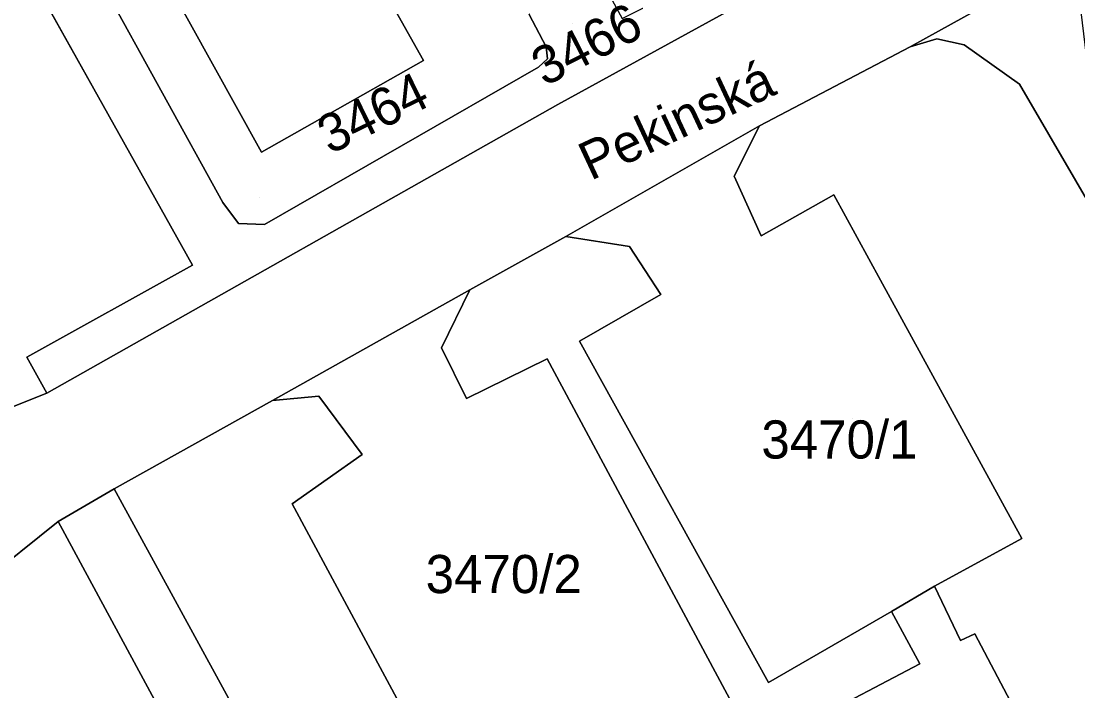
# Model space of a CAD drawing. Extents: x -262715 to -259381, y -1237238 to -1231182.
# Drawn here: x -261471.4 to -261416.1, y -1235520.8 to -1235485.7 of the extents above; entities that cross this region are included whole.
import ezdxf

# ---------------------------------------------------------------- set-up
doc = ezdxf.new("R2010")
doc.units = 0
for name, color, linetype in [('body_kn', 7, 'Continuous'), ('kladpar_druhypozemkov', 7, 'Continuous'), ('kladpar_hranice', 7, 'Continuous'), ('kladpar_parcelnecisla', 7, 'Continuous'), ('kladpar_plochy', 7, 'Continuous'), ('popisy', 7, 'Continuous')]:
    doc.layers.add(name, color=color, linetype=linetype)

msp = doc.modelspace()

# ---------------------------------------------------------------- linework, layer by layer
at = {"layer": 'body_kn'}
for p, q in [((-261423.49, -1235486.65), (-261423.49, -1235486.65)), ((-261443.95, -1235487.06), (-261443.95, -1235487.06)), ((-261424.88, -1235487.06), (-261424.88, -1235487.06)), ((-261422.06, -1235486.95), (-261422.06, -1235486.95)), ((-261450.37, -1235487.77), (-261450.37, -1235487.77)), ((-261443.88, -1235487.69), (-261443.88, -1235487.69)), ((-261444.35, -1235488.12), (-261444.35, -1235488.12)), ((-261419.15, -1235489.02), (-261419.15, -1235489.02)), ((-261419.15, -1235489.02), (-261419.15, -1235489.02)), ((-261443.34, -1235490.09), (-261443.34, -1235490.09)), ((-261432.77, -1235491.2), (-261432.77, -1235491.2)), ((-261458.86, -1235492.58), (-261458.86, -1235492.58)), ((-261434.11, -1235493.83), (-261434.11, -1235493.83)), ((-261428.88, -1235494.81), (-261428.88, -1235494.81)), ((-261428.88, -1235494.81), (-261428.88, -1235494.81)), ((-261460.89, -1235495.22), (-261460.89, -1235495.22)), ((-261460.06, -1235496.32), (-261460.06, -1235496.32)), ((-261458.71, -1235496.37), (-261458.71, -1235496.37)), ((-261442.92, -1235497), (-261442.92, -1235497)), ((-261432.68, -1235496.96), (-261432.68, -1235496.96)), ((-261439.58, -1235497.52), (-261439.58, -1235497.52)), ((-261462.48, -1235498.5), (-261462.48, -1235498.5)), ((-261426.44, -1235499.28), (-261426.44, -1235499.28)), ((-261447.95, -1235499.79), (-261447.95, -1235499.79)), ((-261437.95, -1235500.04), (-261437.95, -1235500.04)), ((-261437.95, -1235500.04), (-261437.95, -1235500.04)), ((-261442.21, -1235502.48), (-261442.21, -1235502.48)), ((-261471.16, -1235503.32), (-261471.16, -1235503.32)), ((-261449.43, -1235502.83), (-261449.43, -1235502.83)), ((-261443.89, -1235503.41), (-261443.89, -1235503.41)), ((-261443.89, -1235503.41), (-261443.89, -1235503.41)), ((-261470.11, -1235505.2), (-261470.11, -1235505.2)), ((-261455.85, -1235505.36), (-261455.85, -1235505.36)), ((-261448.12, -1235505.48), (-261448.12, -1235505.48)), ((-261458.29, -1235505.58), (-261458.29, -1235505.58)), ((-261453.58, -1235508.42), (-261453.58, -1235508.42)), ((-261466.57, -1235510.22), (-261466.57, -1235510.22)), ((-261466.57, -1235510.22), (-261466.57, -1235510.22)), ((-261457.25, -1235511), (-261457.25, -1235511)), ((-261469.51, -1235511.93), (-261469.51, -1235511.93)), ((-261469.51, -1235511.93), (-261469.51, -1235511.93)), ((-261419.04, -1235512.81), (-261419.04, -1235512.81)), ((-261423.61, -1235515.31), (-261423.61, -1235515.31)), ((-261425.86, -1235516.64), (-261425.86, -1235516.64)), ((-261422.25, -1235518.17), (-261422.25, -1235518.17)), ((-261421.49, -1235517.81), (-261421.49, -1235517.81)), ((-261424.38, -1235519.39), (-261424.38, -1235519.39)), ((-261432.31, -1235520.36), (-261432.31, -1235520.36))]:
    msp.add_line(p, q, dxfattribs=at)
at = {"layer": 'kladpar_druhypozemkov'}
for p, q in [((-261442.58, -1235485.86), (-261442.58, -1235485.86)), ((-261458.99, -1235494.98), (-261458.99, -1235494.98)), ((-261427.93, -1235506.53), (-261427.93, -1235506.53)), ((-261444.85, -1235513.54), (-261444.85, -1235513.54))]:
    msp.add_line(p, q, dxfattribs=at)
at = {"layer": 'kladpar_hranice'}
for points in [[(-261500.9, -1235423.36), (-261498.98, -1235427.43), (-261501.9, -1235429.04), (-261472.92, -1235479.85), (-261462.48, -1235498.5), (-261471.16, -1235503.32), (-261470.11, -1235505.2), (-261474.22, -1235506.84), (-261480.34, -1235505.93), (-261486.88, -1235501.6)], [(-261377.82, -1235426.4), (-261370.31, -1235440.22), (-261369.19, -1235443.16), (-261369.47, -1235446.47), (-261370.9, -1235449.61), (-261420.3, -1235477.43), (-261443.34, -1235490.09), (-261470.11, -1235505.2), (-261471.16, -1235503.32), (-261462.48, -1235498.5), (-261472.92, -1235479.85)], [(-261474.22, -1235506.84), (-261470.11, -1235505.2), (-261443.34, -1235490.09), (-261420.3, -1235477.43), (-261370.9, -1235449.61), (-261357.67, -1235441.76), (-261352.68, -1235439.16)], [(-261352.68, -1235439.16), (-261349.41, -1235444.59), (-261351.54, -1235445.98), (-261368.97, -1235455.57), (-261380.71, -1235462.13), (-261384.52, -1235464.26), (-261395.59, -1235470.52), (-261399.31, -1235472.78), (-261411.78, -1235479.68), (-261414.81, -1235481.47), (-261424.88, -1235487.06), (-261432.77, -1235491.2), (-261442.92, -1235497), (-261447.95, -1235499.79), (-261458.29, -1235505.58), (-261466.57, -1235510.22), (-261469.51, -1235511.93), (-261473.53, -1235515.14)], [(-261477.08, -1235466.16), (-261470.37, -1235478.02), (-261460.89, -1235495.22), (-261460.06, -1235496.32), (-261458.71, -1235496.37), (-261444.35, -1235488.12), (-261443.88, -1235487.69), (-261443.95, -1235487.06), (-261445.94, -1235483.26), (-261442.3, -1235481.26), (-261439.97, -1235485.57), (-261435.82, -1235483.49), (-261433.64, -1235482.27), (-261421.07, -1235475.1), (-261418.7, -1235473.78), (-261410.55, -1235469.33)], [(-261448.11, -1235471.56), (-261442.95, -1235480.09), (-261442.3, -1235481.26), (-261445.94, -1235483.26), (-261449.32, -1235485.12), (-261449.92, -1235484.05), (-261451.86, -1235485.14), (-261450.37, -1235487.77), (-261458.86, -1235492.58), (-261467.71, -1235476.61), (-261459.76, -1235472.06), (-261458.19, -1235475), (-261452.66, -1235472.13), (-261451.77, -1235473.6), (-261448.11, -1235471.56)], [(-261445.94, -1235483.26), (-261443.95, -1235487.06), (-261443.88, -1235487.69), (-261444.35, -1235488.12), (-261458.71, -1235496.37), (-261460.06, -1235496.32), (-261460.89, -1235495.22), (-261470.37, -1235478.02), (-261467.71, -1235476.61), (-261458.86, -1235492.58), (-261450.37, -1235487.77), (-261451.86, -1235485.14), (-261449.92, -1235484.05), (-261449.32, -1235485.12), (-261445.94, -1235483.26)], [(-261403.59, -1235514.32), (-261406.6, -1235515.95), (-261408.97, -1235508.66), (-261408.65, -1235507.05), (-261419.15, -1235489.02), (-261422.06, -1235486.95), (-261423.49, -1235486.65), (-261424.88, -1235487.06), (-261414.81, -1235481.47)], [(-261341.24, -1235665.13), (-261362.46, -1235627.19), (-261408.87, -1235541.7), (-261411.85, -1235536.79), (-261410.98, -1235536.3), (-261416.37, -1235525.37), (-261417.25, -1235525.86), (-261421.49, -1235517.81), (-261422.25, -1235518.17), (-261423.61, -1235515.31), (-261419.04, -1235512.81), (-261426.44, -1235499.28), (-261428.88, -1235494.81), (-261432.68, -1235496.96), (-261434.11, -1235493.83), (-261432.77, -1235491.2), (-261424.88, -1235487.06), (-261423.49, -1235486.65), (-261422.06, -1235486.95), (-261419.15, -1235489.02)], [(-261419.15, -1235489.02), (-261408.65, -1235507.05), (-261408.97, -1235508.66), (-261406.6, -1235515.95), (-261405.79, -1235517.45), (-261409.42, -1235519.43), (-261403.63, -1235530.87)], [(-261428.88, -1235494.81), (-261426.44, -1235499.28), (-261419.04, -1235512.81), (-261423.61, -1235515.31), (-261425.86, -1235516.64), (-261432.31, -1235520.36), (-261442.21, -1235502.48), (-261437.95, -1235500.04), (-261439.58, -1235497.52), (-261442.92, -1235497), (-261432.77, -1235491.2), (-261434.11, -1235493.83), (-261432.68, -1235496.96), (-261428.88, -1235494.81)], [(-261437.95, -1235500.04), (-261442.21, -1235502.48), (-261432.31, -1235520.36), (-261425.86, -1235516.64), (-261424.38, -1235519.39), (-261453.28, -1235534.58), (-261466.57, -1235510.22), (-261458.29, -1235505.58), (-261455.85, -1235505.36), (-261453.58, -1235508.42), (-261457.25, -1235511), (-261447.54, -1235529.06), (-261434.21, -1235521.46), (-261443.89, -1235503.41), (-261448.12, -1235505.48), (-261449.43, -1235502.83), (-261447.95, -1235499.79), (-261442.92, -1235497), (-261439.58, -1235497.52), (-261437.95, -1235500.04)], [(-261443.89, -1235503.41), (-261434.21, -1235521.46), (-261447.54, -1235529.06), (-261457.25, -1235511), (-261453.58, -1235508.42), (-261455.85, -1235505.36), (-261458.29, -1235505.58), (-261447.95, -1235499.79), (-261449.43, -1235502.83), (-261448.12, -1235505.48), (-261443.89, -1235503.41)], [(-261352.7, -1235701.57), (-261356.45, -1235698.78), (-261375.96, -1235663.31), (-261392.09, -1235634.4), (-261401.48, -1235640.18), (-261403.28, -1235637.04), (-261396.15, -1235632.64), (-261395.33, -1235631.71), (-261395.49, -1235630.29), (-261406.15, -1235610.79), (-261420.15, -1235585.99), (-261421.33, -1235584.92), (-261422.94, -1235585.32), (-261434.14, -1235591.59), (-261445.58, -1235571), (-261446.9, -1235569.53), (-261442.73, -1235566.89), (-261441.26, -1235564.87), (-261441.82, -1235562.85), (-261455.34, -1235538.18), (-261469.51, -1235511.93), (-261466.57, -1235510.22)], [(-261466.57, -1235510.22), (-261453.28, -1235534.58), (-261424.38, -1235519.39), (-261425.86, -1235516.64), (-261423.61, -1235515.31), (-261422.25, -1235518.17), (-261421.49, -1235517.81), (-261417.25, -1235525.86)], [(-261469.51, -1235511.93), (-261455.34, -1235538.18), (-261441.82, -1235562.85), (-261441.26, -1235564.87), (-261442.73, -1235566.89), (-261446.9, -1235569.53), (-261455.64, -1235559.31), (-261475.01, -1235519.76), (-261473.53, -1235515.14), (-261469.51, -1235511.93)]]:
    msp.add_lwpolyline(points, dxfattribs=at)
at = {"layer": 'kladpar_plochy'}
for p, q in [((-261472.92, -1235479.85), (-261462.48, -1235498.5)), ((-261462.48, -1235498.5), (-261471.16, -1235503.32)), ((-261471.16, -1235503.32), (-261470.11, -1235505.2)), ((-261470.11, -1235505.2), (-261474.22, -1235506.84))]:
    msp.add_line(p, q, dxfattribs=at)
for points in [[(-261474.22, -1235506.84), (-261470.11, -1235505.2), (-261443.34, -1235490.09), (-261420.3, -1235477.43), (-261370.9, -1235449.61), (-261357.67, -1235441.76), (-261352.68, -1235439.16), (-261349.41, -1235444.59), (-261351.54, -1235445.98), (-261368.97, -1235455.57), (-261380.71, -1235462.13), (-261384.52, -1235464.26), (-261395.59, -1235470.52), (-261399.31, -1235472.78), (-261411.78, -1235479.68), (-261414.81, -1235481.47), (-261424.88, -1235487.06), (-261432.77, -1235491.2), (-261442.92, -1235497), (-261447.95, -1235499.79), (-261458.29, -1235505.58), (-261466.57, -1235510.22), (-261469.51, -1235511.93), (-261473.53, -1235515.14)], [(-261370.9, -1235449.61), (-261420.3, -1235477.43), (-261443.34, -1235490.09), (-261470.11, -1235505.2), (-261471.16, -1235503.32), (-261462.48, -1235498.5), (-261472.92, -1235479.85)], [(-261477.08, -1235466.16), (-261470.37, -1235478.02), (-261460.89, -1235495.22), (-261460.06, -1235496.32), (-261458.71, -1235496.37), (-261444.35, -1235488.12), (-261443.88, -1235487.69), (-261443.95, -1235487.06), (-261445.94, -1235483.26), (-261442.3, -1235481.26), (-261439.97, -1235485.57), (-261435.82, -1235483.49), (-261433.64, -1235482.27), (-261421.07, -1235475.1), (-261418.7, -1235473.78), (-261410.55, -1235469.33)], [(-261417.25, -1235525.86), (-261421.49, -1235517.81), (-261422.25, -1235518.17), (-261423.61, -1235515.31), (-261419.04, -1235512.81), (-261426.44, -1235499.28), (-261428.88, -1235494.81), (-261432.68, -1235496.96), (-261434.11, -1235493.83), (-261432.77, -1235491.2), (-261424.88, -1235487.06), (-261423.49, -1235486.65), (-261422.06, -1235486.95), (-261419.15, -1235489.02), (-261408.65, -1235507.05), (-261408.97, -1235508.66), (-261406.6, -1235515.95), (-261405.79, -1235517.45), (-261409.42, -1235519.43), (-261403.63, -1235530.87)], [(-261455.34, -1235538.18), (-261469.51, -1235511.93), (-261466.57, -1235510.22), (-261453.28, -1235534.58), (-261424.38, -1235519.39), (-261425.86, -1235516.64), (-261423.61, -1235515.31), (-261422.25, -1235518.17), (-261421.49, -1235517.81), (-261417.25, -1235525.86)]]:
    msp.add_lwpolyline(points, dxfattribs=at)
for points in [[(-261448.11, -1235471.56), (-261442.95, -1235480.09), (-261442.3, -1235481.26), (-261445.94, -1235483.26), (-261449.32, -1235485.12), (-261449.92, -1235484.05), (-261451.86, -1235485.14), (-261450.37, -1235487.77), (-261458.86, -1235492.58), (-261467.71, -1235476.61), (-261459.76, -1235472.06), (-261458.19, -1235475), (-261452.66, -1235472.13), (-261451.77, -1235473.6)], [(-261445.94, -1235483.26), (-261443.95, -1235487.06), (-261443.88, -1235487.69), (-261444.35, -1235488.12), (-261458.71, -1235496.37), (-261460.06, -1235496.32), (-261460.89, -1235495.22), (-261470.37, -1235478.02), (-261467.71, -1235476.61), (-261458.86, -1235492.58), (-261450.37, -1235487.77), (-261451.86, -1235485.14), (-261449.92, -1235484.05), (-261449.32, -1235485.12)], [(-261414.81, -1235481.47), (-261416.08, -1235484.05), (-261415.67, -1235487.53), (-261407.69, -1235501.13), (-261405.2, -1235503.53), (-261402.1, -1235504.76), (-261399.33, -1235505.09), (-261396.37, -1235504.38), (-261390.89, -1235501.58), (-261389.56, -1235503.89), (-261388.43, -1235506.04), (-261391.44, -1235507.68), (-261403.59, -1235514.32), (-261406.6, -1235515.95), (-261408.97, -1235508.66), (-261408.65, -1235507.05), (-261419.15, -1235489.02), (-261422.06, -1235486.95), (-261423.49, -1235486.65), (-261424.88, -1235487.06)], [(-261428.88, -1235494.81), (-261426.44, -1235499.28), (-261419.04, -1235512.81), (-261423.61, -1235515.31), (-261425.86, -1235516.64), (-261432.31, -1235520.36), (-261442.21, -1235502.48), (-261437.95, -1235500.04), (-261439.58, -1235497.52), (-261442.92, -1235497), (-261432.77, -1235491.2), (-261434.11, -1235493.83), (-261432.68, -1235496.96)], [(-261437.95, -1235500.04), (-261442.21, -1235502.48), (-261432.31, -1235520.36), (-261425.86, -1235516.64), (-261424.38, -1235519.39), (-261453.28, -1235534.58), (-261466.57, -1235510.22), (-261458.29, -1235505.58), (-261455.85, -1235505.36), (-261453.58, -1235508.42), (-261457.25, -1235511), (-261447.54, -1235529.06), (-261434.21, -1235521.46), (-261443.89, -1235503.41), (-261448.12, -1235505.48), (-261449.43, -1235502.83), (-261447.95, -1235499.79), (-261442.92, -1235497), (-261439.58, -1235497.52)], [(-261443.89, -1235503.41), (-261434.21, -1235521.46), (-261447.54, -1235529.06), (-261457.25, -1235511), (-261453.58, -1235508.42), (-261455.85, -1235505.36), (-261458.29, -1235505.58), (-261447.95, -1235499.79), (-261449.43, -1235502.83), (-261448.12, -1235505.48)], [(-261469.51, -1235511.93), (-261455.34, -1235538.18), (-261441.82, -1235562.85), (-261441.26, -1235564.87), (-261442.73, -1235566.89), (-261446.9, -1235569.53), (-261455.64, -1235559.31), (-261475.01, -1235519.76), (-261473.53, -1235515.14)]]:
    msp.add_lwpolyline(points, close=True, dxfattribs=at)

# ---------------------------------------------------------------- texts
at = {"layer": 'kladpar_parcelnecisla'}
for s, rotation, p in [('3466', 27, (-261444.038, -1235489.159)), ('3464', 26, (-261455.279, -1235492.717))]:
    msp.add_text(s, height=2, rotation=rotation, dxfattribs=at).set_placement(p)
for s, p in [('3470/1', (-261432.677, -1235508.63)), ('3470/2', (-261450.263, -1235515.68))]:
    msp.add_text(s, height=2, dxfattribs=at).set_placement(p)
at = {"layer": 'popisy'}
msp.add_text('Pekinská', height=2, rotation=25, dxfattribs=at).set_placement((-261441.621, -1235494.092))

doc.saveas('drawing.dxf')
